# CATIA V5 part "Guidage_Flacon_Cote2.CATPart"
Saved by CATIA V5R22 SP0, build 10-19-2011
Part number: Guidage_Flacon_Cote
Bounding box of the stored display mesh (mm): x 0 to 10, y -49.5 to 49.5, z 0 to 15
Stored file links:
  C:\Users\La forge\Desktop\CAO_PER_pick&place_2023A\Sous_Ensemble_Flacon\Guidage_Flacon_Cote2.CATPart
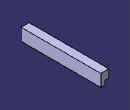
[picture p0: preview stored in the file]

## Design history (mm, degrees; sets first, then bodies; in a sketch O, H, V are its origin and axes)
Body1 (main body)
  Sketch1 on yz-plane, origin (0, 0, 0), H (0, 1, 0), V (0, 0, 1)
    point P1 (49.5, 0)
    line L1 (49.5, 0) -> (-49.5, 0)
    line L2 (-49.5, 0) -> (-49.5, 15)
    line L3 (-49.5, 15) -> (49.5, 15)
    line L4 (49.5, 15) -> (49.5, 0)
    length L3 = 99
    length L4 = 15
    coincidence: P1 H
    horizontal: L1 H, L3 H
    vertical: L2 V, L4 V
    equidistance: L4 L2 O
  Pad1: profile Sketch1, direction (1, 0, 0), length 5
  Sketch2 on end face of Pad1, origin (5, 0, 0), H (0, 1, 0), V (0, 0, 1)
    point P1 (-49.5, 0)
    line L1 (-49.5, 0) -> (-34.5, 0)
    line L2 (-34.5, 0) -> (-34.5, 5)
    line L3 (-34.5, 5) -> (-49.5, 5)
    line L4 (-49.5, 5) -> (-49.5, 0)
    reference projected point E1 (-49.5, 0) from vertex [face of Pad1 from Sketch1.L1 | end face of Pad1 | face of Pad1 from Sketch1.L2]
    length L2 = 5
    length L3 = 15
    coincidence: P1 H, P1 E1
    horizontal: L1 H, L3 H
    vertical: L2 V, L4 V
  Pocket1: profile Sketch2, direction (-1, 0, 0), through (limit type 3)
  RectPattern1: of Pocket1, direction 1 instances 4, spacing 28, along end face of Pad1
  Sketch3 on end face of Pad1, origin (5, 0, 0), H (0, 1, 0), V (0, 0, 1)
    line L1 (-44.5, 5) -> (-49.5, 5)
    line L2 (-49.5, 5) -> (-49.5, 10)
    line L3 (-49.5, 10) -> (-44.5, 10)
    line L4 (-44.5, 10) -> (-44.5, 5)
    reference projected line E1 (-34.5, 5) -> (-49.5, 5) from edge [end face of Pad1 | face of Pocket1 from Sketch2.L3]
    reference projected line E2 (-49.5, 15) -> (-49.5, 0) from edge [face of Pad1 from Sketch1.L2 | end face of Pad1]
    length L2 = 5
    length L3 = 5
    horizontal: L1 H, L3 H
    vertical: L2 V, L4 V
    coincidence: L1 E1, L2 E2
  Pocket2: profile Sketch3, direction (-1, 0, 0), through (limit type 3)
  Sketch4 on end face of Pad1, origin (5, 0, 0), H (0, 1, 0), V (0, 0, 1)
    point P1 (49.5, 0)
    line L1 (49.5, 0) -> (-49.5, 0)
    line L2 (-49.5, 0) -> (-49.5, 15)
    line L3 (-49.5, 15) -> (49.5, 15)
    line L4 (49.5, 15) -> (49.5, 0)
    length L3 = 99
    length L4 = 15
    coincidence: P1 H
    horizontal: L1 H, L3 H
    vertical: L2 V, L4 V
    equidistance: L4 L2 O
  Pad2: profile Sketch4, direction (1, 0, 0), length 5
